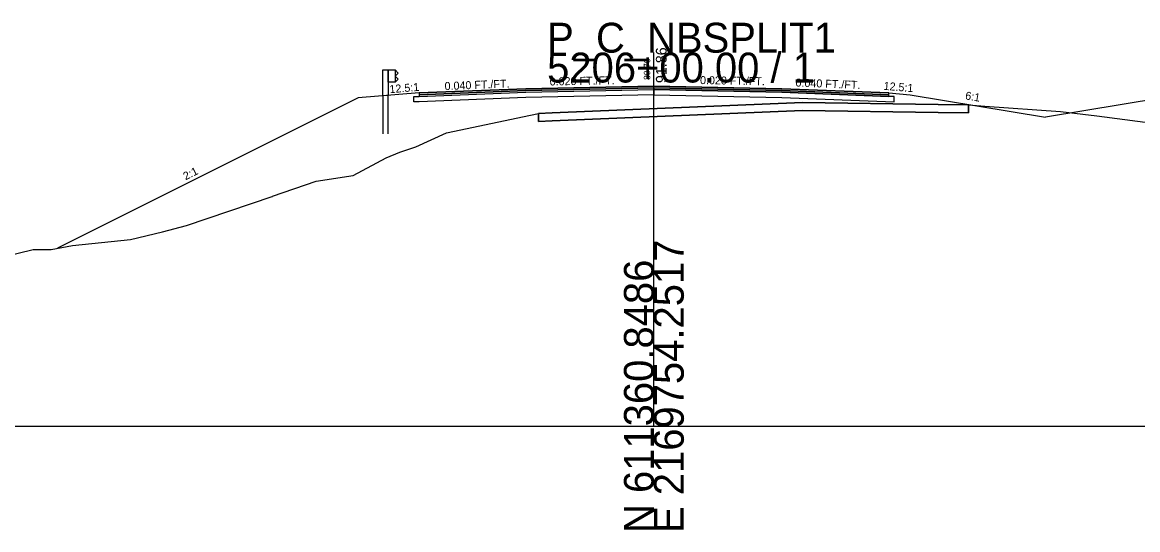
# Model space of a CAD drawing. Extents: x -26 to 1303, y -3010 to 12038.
# Drawn here: x 1090.8 to 1195.3, y 3990.3 to 4037.8 of the extents above; entities that cross this region are included whole.
import ezdxf

# ---------------------------------------------------------------- set-up
doc = ezdxf.new("R2010")
doc.units = 0
for name, color, linetype in [('RD_GPK_XS_Cell', 7, 'Continuous'), ('RD_PD_Final_TrvlWay', 7, 'Continuous'), ('RD_XS_Base', 7, 'Continuous'), ('RD_XS_ExGround', 7, 'Continuous'), ('RD_XS_ExPaveRet', 7, 'Continuous'), ('RD_XS_GR', 7, 'Continuous'), ('RD_XS_Greenside', 7, 'Continuous'), ('RD_XS_Pave', 7, 'Continuous'), ('RD_XS_PaveOvlay_CP', 7, 'Continuous'), ('RD_XS_TieSlope', 7, 'Continuous'), ('RD_XS_TX_Elev_EX', 7, 'Continuous'), ('RD_XS_TX_Elev_PR', 7, 'Continuous'), ('RD_XS_TX_ShdSlope', 7, 'Continuous'), ('RD_XS_TX_Slope', 7, 'Continuous')]:
    doc.layers.add(name, color=color, linetype=linetype)

msp = doc.modelspace()

# ---------------------------------------------------------------- linework, layer by layer
at = {"layer": 'RD_GPK_XS_Cell'}
for p, q in [((1150, 4000), (1150, 4035)), ((1000, 4000), (1150, 4000)), ((1150, 4000), (1300, 4000))]:
    msp.add_line(p, q, dxfattribs=at)
at = {"layer": 'RD_PD_Final_TrvlWay'}
for p, q in [((1125.11, 4030.99), (1124.61, 4030.95)), ((1124.61, 4030.95), (1124.61, 4027.38)), ((1125.11, 4027.38), (1125.11, 4030.99))]:
    msp.add_line(p, q, dxfattribs=at)
at = {"layer": 'RD_XS_Base'}
for p, q in [((1138, 4031.3), (1150, 4031.54)), ((1150, 4031.54), (1150, 4031.7)), ((1150, 4031.7), (1150, 4031.04)), ((1150, 4031.54), (1150, 4031.04)), ((1162, 4031.3), (1150, 4031.54)), ((1150, 4031.54), (1150, 4031.54)), ((1127.5, 4030.88), (1128, 4030.9)), ((1127.5, 4030.38), (1127.5, 4030.88)), ((1127.5, 4030.88), (1127.5, 4030.88)), ((1128, 4030.4), (1127.5, 4030.38)), ((1128, 4030.9), (1138, 4031.3)), ((1128, 4030.9), (1128, 4030.9)), ((1138, 4030.8), (1128, 4030.4)), ((1128, 4030.4), (1128, 4030.4)), ((1138, 4031.3), (1138, 4031.3)), ((1150, 4031.04), (1138, 4030.8)), ((1138, 4030.8), (1138, 4030.8)), ((1150, 4031.04), (1150, 4031.04)), ((1150, 4031.04), (1150, 4031.04)), ((1150, 4031.04), (1162, 4030.8)), ((1172, 4030.9), (1162, 4031.3)), ((1162, 4030.8), (1172.5, 4030.38)), ((1164, 4031.22), (1164, 4031.22)), ((1164, 4030.72), (1164, 4030.72)), ((1172.5, 4030.88), (1172, 4030.9)), ((1172, 4030.9), (1172, 4030.9)), ((1172.5, 4030.38), (1172.5, 4030.88)), ((1172.5, 4030.88), (1172.5, 4030.88)), ((1127.5, 4030.38), (1127.5, 4030.38)), ((1127.5, 4030.38), (1127.5, 4030.38)), ((1172.5, 4030.38), (1172.5, 4030.38)), ((1172.5, 4030.38), (1172.5, 4030.38))]:
    msp.add_line(p, q, dxfattribs=at)
at = {"layer": 'RD_XS_ExGround'}
msp.add_lwpolyline([(1080.94, 4013.89), (1091.84, 4016.57), (1093.53, 4016.57), (1095.54, 4016.93), (1100.96, 4017.5), (1103.97, 4018.2), (1106.21, 4018.79), (1114.24, 4021.53), (1114.26, 4021.53), (1114.28, 4021.54), (1114.28, 4021.54), (1118.36, 4022.95), (1121.82, 4023.5), (1124.91, 4025.14), (1126.19, 4025.68), (1127.7, 4026.17), (1130.58, 4027.5), (1138.43, 4029.14), (1139.18, 4029.3), (1140.46, 4029.36), (1163.92, 4030.34), (1176.64, 4030.15), (1179.48, 4030.1), (1181, 4029.99), (1188.11, 4029.5), (1191.51, 4029.08), (1196.02, 4028.49)], dxfattribs=at)
at = {"layer": 'RD_XS_ExPaveRet'}
for p, q in [((1176.64, 4030.15), (1163.92, 4030.34)), ((1179.48, 4030.1), (1176.64, 4030.15))]:
    msp.add_line(p, q, dxfattribs=at)
for points in [[(1179.48, 4030.1), (1179.48, 4030.1), (1179.48, 4029.35), (1179.48, 4029.35), (1176.64, 4029.4), (1176.64, 4029.4), (1163.92, 4029.59), (1163.92, 4029.59), (1140.46, 4028.61), (1140.46, 4028.61), (1139.18, 4028.55), (1139.18, 4028.55), (1139.18, 4029.3), (1140.46, 4029.36), (1140.46, 4029.36), (1163.92, 4030.34), (1163.92, 4030.34), (1176.64, 4030.15), (1176.64, 4030.15), (1179.48, 4030.1), (1179.48, 4030.1)], [(1163.92, 4030.34), (1140.46, 4029.36), (1139.18, 4029.3), (1139.18, 4028.55), (1140.46, 4028.61), (1163.92, 4029.59), (1176.64, 4029.4), (1179.48, 4029.35), (1179.48, 4029.35), (1179.48, 4030.1), (1179.48, 4030.1)]]:
    msp.add_lwpolyline(points, dxfattribs=at)
at = {"layer": 'RD_XS_GR'}
for points in [[(1125.11, 4033.38), (1125.11, 4030.99), (1124.61, 4030.95), (1124.61, 4033.38), (1124.86, 4033.38), (1125.11, 4033.38)], [(1125.77, 4033.38), (1125.77, 4032.22), (1125.11, 4032.22), (1125.11, 4033.38), (1125.77, 4033.38)], [(1126.04, 4033.09), (1125.77, 4033.38), (1125.77, 4032.22), (1125.77, 4032.22), (1125.77, 4032.22), (1126.04, 4032.51), (1126.04, 4032.51), (1125.77, 4032.8), (1125.77, 4032.8), (1126.04, 4033.09), (1126.04, 4033.09)]]:
    msp.add_lwpolyline(points, dxfattribs=at)
at = {"layer": 'RD_XS_Greenside'}
for p, q in [((1122.29, 4030.76), (1094.12, 4016.68)), ((1174, 4031.06), (1186.68, 4028.95)), ((1197.45, 4030.74), (1186.68, 4028.95))]:
    msp.add_line(p, q, dxfattribs=at)
at = {"layer": 'RD_XS_Pave'}
for p, q in [((1138, 4031.62), (1128, 4031.22)), ((1138, 4031.46), (1128, 4031.06)), ((1128, 4031.06), (1138, 4031.46)), ((1150, 4031.86), (1138, 4031.62)), ((1150, 4031.7), (1138, 4031.46)), ((1138, 4031.46), (1150, 4031.7)), ((1138, 4031.62), (1138, 4031.62)), ((1138, 4031.3), (1150, 4031.54)), ((1138, 4031.46), (1138, 4031.46)), ((1138, 4031.46), (1138, 4031.46)), ((1162, 4031.62), (1150, 4031.86)), ((1150, 4031.54), (1150, 4031.7)), ((1150, 4031.7), (1162, 4031.46)), ((1162, 4031.46), (1150, 4031.7)), ((1150, 4031.7), (1150, 4031.54)), ((1150, 4031.54), (1150, 4031.54)), ((1150, 4031.54), (1150, 4031.54)), ((1150, 4031.54), (1162, 4031.3)), ((1172, 4031.22), (1162, 4031.62)), ((1162, 4031.46), (1172, 4031.06)), ((1172, 4031.06), (1162, 4031.46)), ((1164, 4031.54), (1164, 4031.54)), ((1128, 4030.9), (1138, 4031.3)), ((1128, 4031.22), (1128, 4031.22)), ((1128, 4031.22), (1128, 4031.06)), ((1128, 4031.06), (1128, 4031.06)), ((1128, 4031.06), (1128, 4030.9)), ((1128, 4031.06), (1128, 4031.06)), ((1128, 4031.06), (1128, 4031.06)), ((1128, 4030.9), (1128, 4030.9)), ((1128, 4030.9), (1128, 4030.9)), ((1138, 4031.3), (1138, 4031.3)), ((1162, 4031.3), (1172, 4030.9)), ((1164, 4031.38), (1164, 4031.38)), ((1164, 4031.38), (1164, 4031.38)), ((1164, 4031.22), (1164, 4031.22)), ((1172, 4031.06), (1172, 4031.22)), ((1172, 4031.22), (1172, 4031.22)), ((1172, 4031.06), (1172, 4031.06)), ((1172, 4031.06), (1172, 4031.06)), ((1172, 4030.9), (1172, 4031.06)), ((1172, 4031.06), (1172, 4031.06)), ((1172, 4030.9), (1172, 4030.9)), ((1172, 4030.9), (1172, 4030.9))]:
    msp.add_line(p, q, dxfattribs=at)
at = {"layer": 'RD_XS_PaveOvlay_CP'}
for p, q in [((1128, 4031.22), (1138, 4031.62)), ((1138, 4031.62), (1150, 4031.86)), ((1150, 4031.86), (1162, 4031.62)), ((1162, 4031.62), (1172, 4031.22))]:
    msp.add_line(p, q, dxfattribs=at)
at = {"layer": 'RD_XS_TieSlope'}
for p, q in [((1128, 4031.22), (1122.29, 4030.76)), ((1172, 4031.22), (1174, 4031.06))]:
    msp.add_line(p, q, dxfattribs=at)

# ---------------------------------------------------------------- texts
at = {"layer": 'RD_GPK_XS_Cell'}
for s, p in [('P_C_NBSPLIT1', (1140, 4035)), ('5206+00.00 / 1', (1140, 4032.2))]:
    msp.add_text(s, height=2.8, dxfattribs=at).set_placement(p)
for s, p in [('E 2169754.2517', (1152.8, 3990)), ('N 611360.8486', (1150, 3990))]:
    msp.add_text(s, height=2.8, rotation=90, dxfattribs=at).set_placement(p)
at = {"layer": 'RD_XS_TX_Elev_EX'}
msp.add_text('89.76', height=0.6, rotation=90, dxfattribs=at).set_placement((1149.66, 4032.44))
at = {"layer": 'RD_XS_TX_Elev_PR'}
msp.add_text('91.86', height=1, rotation=90, dxfattribs=at).set_placement((1151.19, 4032.15))
at = {"layer": 'RD_XS_TX_ShdSlope'}
for rotation, p in [(4.5739, (1125.26, 4031.2)), (355.4261, (1171.5, 4031.52))]:
    msp.add_text('12.5:1', height=0.75, rotation=rotation, dxfattribs=at).set_placement(p)
at = {"layer": 'RD_XS_TX_Slope'}
for s, rotation, p in [('0.020 FT./FT.', 1.1458, (1140.25, 4031.92)), ('0.020 FT./FT.', 358.8542, (1154.32, 4032.06)), ('0.040 FT./FT.', 357.7094, (1163.26, 4031.83)), ('0.040 FT./FT.', 2.2906, (1130.41, 4031.49)), ('6:1', 350.5377, (1179.13, 4030.63)), ('2:1', 26.5651, (1106.13, 4023.03))]:
    msp.add_text(s, height=0.75, rotation=rotation, dxfattribs=at).set_placement(p)

doc.saveas('drawing.dxf')
